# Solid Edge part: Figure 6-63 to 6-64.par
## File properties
Author: Ashutosh-CADCIM
Template: Iso Metric Part.par
Last saved by: ASUS-CADCIM Tech
Revision: 3
Application: Solid Edge
Accuracy: 0.990
Username: Ashutosh-CADCIM
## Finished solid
Body 1: solid body, 10 faces, 24 edges, 16 vertices.
  Faces by surface: plane 10
  Edges by curve: line 24
Bounding box of the edges (mm): 150.000 x 175.000 x 20.000, from (-75, -80, -10) to (75, 95, 10).
Planar faces by outward normal: +x 2, +y 2, +z 1, -x 2, -y 2, -z 1
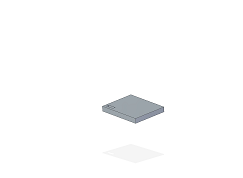
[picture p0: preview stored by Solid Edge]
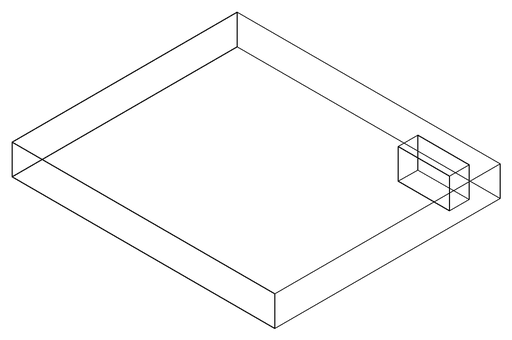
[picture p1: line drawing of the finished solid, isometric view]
